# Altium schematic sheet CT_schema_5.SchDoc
size 339 x 183 mm
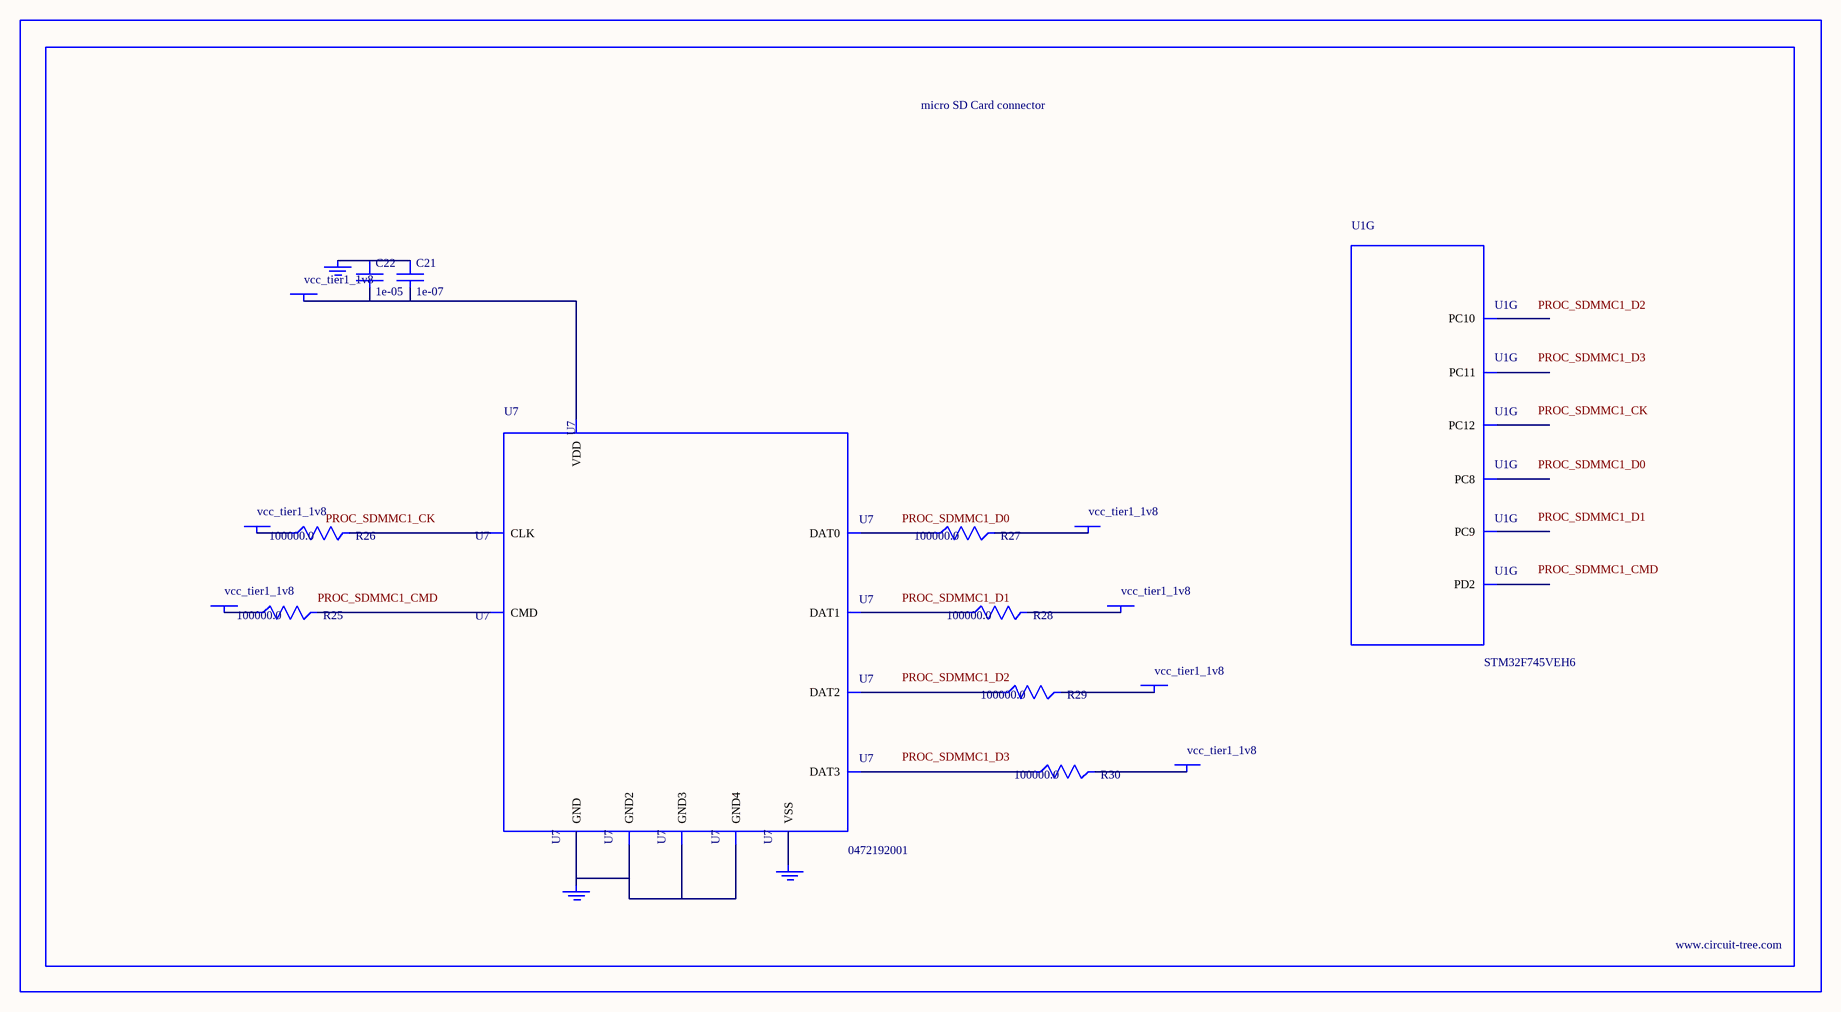
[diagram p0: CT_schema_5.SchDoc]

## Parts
BORDER4  (no value)
C21  1e-07  [C0402]
C22  1e-05  [C0805]
GND_INSTANCE_4_0  (no value)
GND_INSTANCE_4_1  (no value)
GND_INSTANCE_4_2  (no value)
POWER_INSTANCE_4_0  vcc_tier1_1v8
POWER_INSTANCE_4_1  vcc_tier1_1v8
POWER_INSTANCE_4_2  vcc_tier1_1v8
POWER_INSTANCE_4_3  vcc_tier1_1v8
POWER_INSTANCE_4_4  vcc_tier1_1v8
POWER_INSTANCE_4_5  vcc_tier1_1v8
POWER_INSTANCE_4_6  vcc_tier1_1v8
R25  100000.0  [R0603]
R26  100000.0  [R0603]
R27  100000.0  [R0603]
R28  100000.0  [R0603]
R29  100000.0  [R0603]
R30  100000.0  [R0603]
U1  STM32F745VEH6  [TFBGA100]  (part G of 10)
U7  0472192001  [MOLEX_47219-2001]

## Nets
NetC21_1: C21.1 C22.1 GND_INSTANCE_4_0.0(GND)
NetC21_2: C21.2 C22.2 POWER_INSTANCE_4_3.0(PWR) U7.4(VDD)
NetGND_INSTANCE_4_1_0: GND_INSTANCE_4_1.0(GND) U7.6(VSS)
NetGND_INSTANCE_4_2_0: GND_INSTANCE_4_2.0(GND) U7.G1(GND) U7.G2(GND2) U7.G3(GND3) U7.G4(GND4)
NetPOWER_INSTANCE_4_0_0: POWER_INSTANCE_4_0.0(PWR) R29.2
NetPOWER_INSTANCE_4_1_0: POWER_INSTANCE_4_1.0(PWR) R30.2
NetPOWER_INSTANCE_4_2_0: POWER_INSTANCE_4_2.0(PWR) R25.1
NetPOWER_INSTANCE_4_4_0: POWER_INSTANCE_4_4.0(PWR) R26.1
NetPOWER_INSTANCE_4_5_0: POWER_INSTANCE_4_5.0(PWR) R27.2
NetPOWER_INSTANCE_4_6_0: POWER_INSTANCE_4_6.0(PWR) R28.2
NetR25_2: R25.2 U7.3(CMD)
NetR26_2: R26.2 U7.5(CLK)
NetR27_1: R27.1 U7.7(DAT0)
NetR28_1: R28.1 U7.8(DAT1)
NetR29_1: R29.1 U7.1(DAT2)
NetR30_1: R30.1 U7.2(DAT3)

Not connected (* = marked no-connect by the designer): U1 B7(PD2) B8(PC11) B9(PC10) C8(PC12) E9(PC9) F9(PC8)

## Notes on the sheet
- Labels drawn without touching a wire or pin: PROC_SDMMC1_CK, PROC_SDMMC1_CMD, PROC_SDMMC1_D0, PROC_SDMMC1_D1, PROC_SDMMC1_D2, PROC_SDMMC1_D3

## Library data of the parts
BORDER4 = BORDER_PAGE4
C21 = C0402C104K3RACTU
C22 = C0805C106K8RACTU
GND_INSTANCE_4_0-GND_INSTANCE_4_2 = GND
POWER_INSTANCE_4_0-POWER_INSTANCE_4_6 = PWR
R25-R30 = RC0603JR-07100KL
